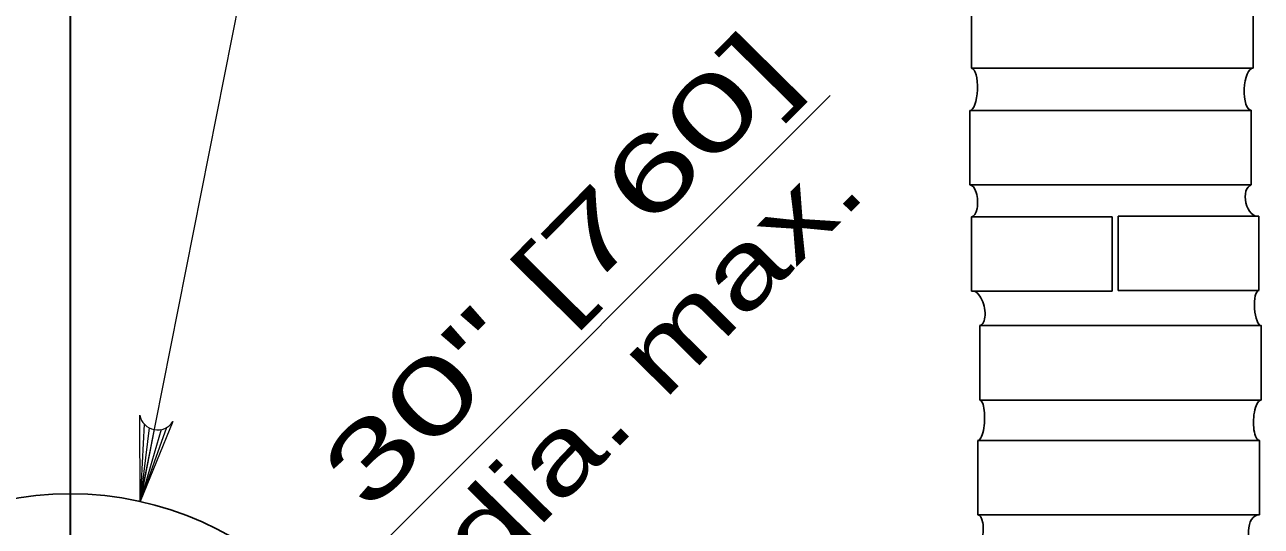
# Model space of a CAD drawing. Extents: x 1083.1 to 1117.1, y 697.4 to 741.4.
# Drawn here: x 1099.373 to 1101.961, y 731.469 to 732.519 of the extents above; entities that cross this region are included whole.
import ezdxf
from ezdxf.enums import TextEntityAlignment as Align

# ---------------------------------------------------------------- set-up
doc = ezdxf.new("R2010")
doc.units = 0
doc.header["$LTSCALE"] = 0.062
doc.layers.add('1', color=7, linetype='Continuous', lineweight=13)

msp = doc.modelspace()

# ---------------------------------------------------------------- linework, layer by layer
at = {"layer": '1', "lineweight": 35}
msp.add_line((1099.46825, 732.65125), (1099.46825, 731.18483), dxfattribs=at)
at = {"layer": '1', "lineweight": 25}
for p, q in [((1101.35517, 732.42792), (1101.35517, 732.58392)), ((1101.94442, 732.42792), (1101.35517, 732.42792)), ((1101.35133, 732.18358), (1101.35133, 732.3395)), ((1101.94058, 732.18358), (1101.35133, 732.18358)), ((1101.64933, 732.117), (1101.35475, 732.117)), ((1101.35475, 731.96108), (1101.35475, 732.117)), ((1101.64933, 731.96108), (1101.64933, 732.117)), ((1101.95633, 732.11833), (1101.66175, 732.11833)), ((1101.66175, 731.96233), (1101.66175, 732.11833)), ((1101.95633, 731.96233), (1101.95633, 732.11833)), ((1101.64933, 731.96108), (1101.35475, 731.96108)), ((1101.95633, 731.96233), (1101.66175, 731.96233)), ((1101.37217, 731.73292), (1101.37217, 731.88892)), ((1101.96142, 731.73292), (1101.37217, 731.73292)), ((1101.36842, 731.49258), (1101.36842, 731.6485)), ((1101.95758, 731.49258), (1101.36842, 731.49258))]:
    msp.add_line(p, q, dxfattribs=at)
at = {"layer": '1'}
for p, q in [((1099.06267, 730.3735), (1101.05933, 732.37067)), ((1099.6235, 731.68225), (1099.61508, 731.52067)), ((1099.67017, 731.67517), (1099.61508, 731.52067)), ((1099.63333, 731.67483), (1099.61508, 731.52067)), ((1099.64417, 731.67108), (1099.61508, 731.52067)), ((1099.65883, 731.67108), (1099.61508, 731.52067))]:
    msp.add_line(p, q, dxfattribs=at)
for points in [[(1099.61508, 731.52067), (1099.91942, 733.06), (1100.27075, 733.06)], [(1099.68342, 731.68775), (1099.61508, 731.52067), (1099.61392, 731.70117)]]:
    msp.add_lwpolyline(points, dxfattribs=at)
at = {"layer": '1', "lineweight": 25}
for points in [[(1101.94442, 732.42792), (1101.94442, 732.58392), (1101.35517, 732.58392)], [(1101.94058, 732.18358), (1101.94058, 732.3395), (1101.35133, 732.3395)], [(1101.96142, 731.73292), (1101.96142, 731.88892), (1101.37217, 731.88892)], [(1101.95758, 731.49258), (1101.95758, 731.6485), (1101.36842, 731.6485)]]:
    msp.add_lwpolyline(points, dxfattribs=at)
at = {"layer": '1'}
msp.add_arc((1099.65136, 731.70852), 0.0382, 191.15654, 326.98267, dxfattribs=at)
at = {"layer": '1', "lineweight": 25}
for centre, major_axis, ratio, start_param, end_param in [((1101.35325, 732.38373), (0.00187, 0.0442), 0.320957, 3.1397455, 6.2813381), ((1101.94248, 732.38373), (-0.00185, -0.0442), 0.379685, 3.1393036, 6.2808962), ((1101.35304, 732.15029), (0.00164, -0.03329), 0.439649, 0.003329, 3.1449217), ((1101.94846, 732.15094), (-0.00739, 0.03275), 0.590174, 0.0247979, 3.1663905), ((1101.36345, 731.92497), (0.0084, -0.03617), 0.496325, 0.0180525, 3.1596452), ((1101.95887, 731.92562), (0.0025, -0.03674), 0.312466, 3.1444636, 6.2860562), ((1101.37027, 731.69073), (-0.00187, -0.0422), 0.283611, 6.2815177, 9.4231104), ((1101.95951, 731.69073), (-0.00186, -0.0422), 0.339712, 3.1395162, 6.2811089), ((1101.36722, 731.46039), (0.00114, 0.03219), 0.380062, 3.1396459, 6.2812386), ((1101.95571, 731.45841), (-0.00041, -0.03418), 0.615958, 3.1400459, 6.2816385)]:
    msp.add_ellipse(centre, major_axis=major_axis, ratio=ratio, start_param=start_param, end_param=end_param, dxfattribs=at)
msp.add_ellipse((1099.46858, 730.78657), major_axis=(0, 0.75008), ratio=0.944544, dxfattribs=at)

# ---------------------------------------------------------------- texts
at = {"layer": '1'}
for s, width, p in [('30" [760]', 1.55, (1100.54353, 731.95084)), ('dia. max.', 1.35, (1100.73846, 731.7583))]:
    msp.add_text(s, height=0.156, rotation=45.34, dxfattribs=dict(at, width=width)).set_placement(p, align=Align.CENTER)

doc.saveas('drawing.dxf')
